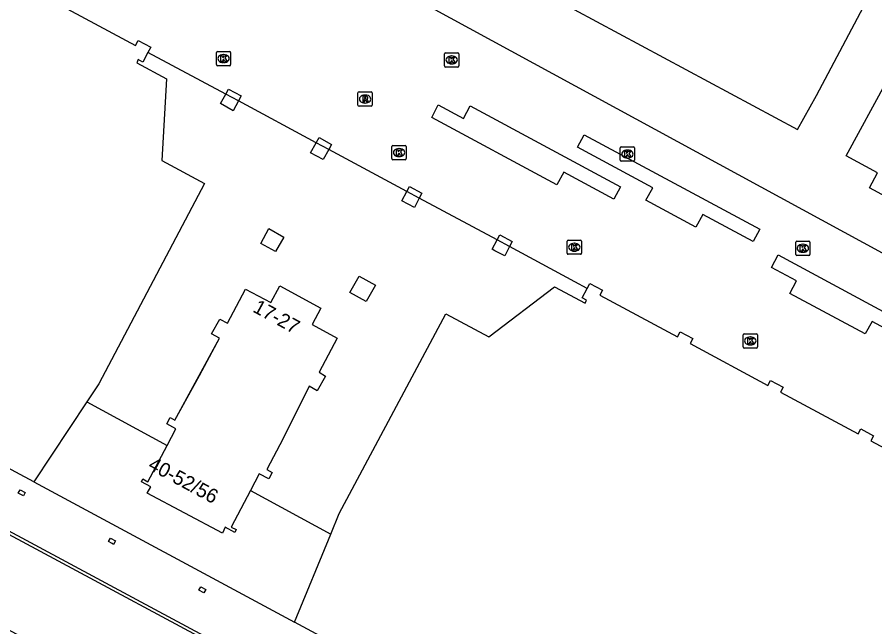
# Model space of a CAD drawing. Extents: x 159489 to 160304, y 383826 to 384530.
# Drawn here: x 159831.2 to 159891.4, y 384203.6 to 384246.5 of the extents above; entities that cross this region are included whole.
import ezdxf

# ---------------------------------------------------------------- set-up
doc = ezdxf.new("R2010")
doc.units = 0
for name, color, linetype in [('IMGEO_Kolk', 7, 'Continuous'), ('IMGEO_Lijnafwatering', 7, 'Continuous'), ('IMGEO_Pand', 7, 'Continuous'), ('IMGEO_Pand_nummerreeks', 7, 'Continuous'), ('IMGEO_Pand_overbouw', 7, 'Continuous'), ('IMGEO_Rioolput', 7, 'Continuous'), ('IMGEO_Voetpad_gesloten', 7, 'Continuous'), ('IMGEO_Voetpad_open', 7, 'Continuous')]:
    doc.layers.add(name, color=color, linetype=linetype)

msp = doc.modelspace()

# ---------------------------------------------------------------- linework, layer by layer
at = {"layer": 'IMGEO_Kolk'}
for p, q in [((159845.183, 384243.138), (159845.183, 384243.99)), ((159845.258, 384244.064), (159846.11, 384244.064)), ((159845.671, 384243.844), (159845.696, 384243.844)), ((159846.184, 384243.99), (159846.184, 384243.138)), ((159861.205, 384243.046), (159861.205, 384243.898)), ((159861.28, 384243.972), (159862.132, 384243.972)), ((159862.206, 384243.898), (159862.206, 384243.046)), ((159845.694, 384243.284), (159845.669, 384243.284)), ((159861.716, 384243.192), (159861.691, 384243.192)), ((159861.693, 384243.752), (159861.718, 384243.752)), ((159846.11, 384243.064), (159845.258, 384243.064)), ((159862.132, 384242.972), (159861.28, 384242.972)), ((159857.51, 384236.536), (159857.51, 384237.388)), ((159857.585, 384237.462), (159858.437, 384237.462)), ((159857.998, 384237.242), (159858.023, 384237.242)), ((159858.511, 384237.388), (159858.511, 384236.536)), ((159873.545, 384236.432), (159873.545, 384237.284)), ((159873.62, 384237.358), (159874.472, 384237.358)), ((159874.546, 384237.284), (159874.546, 384236.432)), ((159858.021, 384236.682), (159857.996, 384236.682)), ((159874.056, 384236.578), (159874.031, 384236.578)), ((159874.033, 384237.138), (159874.058, 384237.138)), ((159858.437, 384236.462), (159857.585, 384236.462)), ((159874.472, 384236.358), (159873.62, 384236.358)), ((159869.819, 384229.889), (159869.819, 384230.741)), ((159869.894, 384230.815), (159870.746, 384230.815)), ((159870.307, 384230.595), (159870.332, 384230.595)), ((159870.82, 384230.741), (159870.82, 384229.889)), ((159885.869, 384229.812), (159885.869, 384230.664)), ((159885.944, 384230.738), (159886.796, 384230.738)), ((159886.87, 384230.664), (159886.87, 384229.812)), ((159870.33, 384230.035), (159870.305, 384230.035)), ((159886.38, 384229.958), (159886.355, 384229.958)), ((159886.357, 384230.518), (159886.382, 384230.518)), ((159870.746, 384229.815), (159869.894, 384229.815)), ((159886.796, 384229.738), (159885.944, 384229.738)), ((159882.177, 384223.308), (159882.177, 384224.16)), ((159882.252, 384224.234), (159883.104, 384224.234)), ((159882.665, 384224.014), (159882.69, 384224.014)), ((159883.178, 384224.16), (159883.178, 384223.308)), ((159882.688, 384223.454), (159882.663, 384223.454)), ((159883.104, 384223.234), (159882.252, 384223.234))]:
    msp.add_line(p, q, dxfattribs=at)
for points in [[(159845.183, 384243.138), (159845.183, 384243.99)], [(159845.258, 384244.064), (159846.11, 384244.064)], [(159846.184, 384243.99), (159846.184, 384243.138)], [(159861.205, 384243.046), (159861.205, 384243.898)], [(159861.28, 384243.972), (159862.132, 384243.972)], [(159862.206, 384243.898), (159862.206, 384243.046)], [(159845.504, 384243.764), (159845.627, 384243.764), (159845.627, 384243.613), (159845.757, 384243.764), (159845.921, 384243.764), (159845.775, 384243.613), (159845.928, 384243.364), (159845.776, 384243.364), (159845.691, 384243.528), (159845.627, 384243.461), (159845.627, 384243.364), (159845.504, 384243.364), (159845.504, 384243.764)], [(159861.526, 384243.672), (159861.649, 384243.672), (159861.649, 384243.521), (159861.779, 384243.672), (159861.943, 384243.672), (159861.797, 384243.521), (159861.95, 384243.272), (159861.798, 384243.272), (159861.713, 384243.436), (159861.649, 384243.369), (159861.649, 384243.272), (159861.526, 384243.272), (159861.526, 384243.672)], [(159846.11, 384243.064), (159845.258, 384243.064)], [(159862.132, 384242.972), (159861.28, 384242.972)], [(159857.51, 384236.536), (159857.51, 384237.388)], [(159857.585, 384237.462), (159858.437, 384237.462)], [(159858.511, 384237.388), (159858.511, 384236.536)], [(159873.545, 384236.432), (159873.545, 384237.284)], [(159873.62, 384237.358), (159874.472, 384237.358)], [(159874.546, 384237.284), (159874.546, 384236.432)], [(159857.831, 384237.162), (159857.954, 384237.162), (159857.954, 384237.011), (159858.084, 384237.162), (159858.248, 384237.162), (159858.102, 384237.011), (159858.255, 384236.762), (159858.103, 384236.762), (159858.018, 384236.926), (159857.954, 384236.859), (159857.954, 384236.762), (159857.831, 384236.762), (159857.831, 384237.162)], [(159873.866, 384237.058), (159873.989, 384237.058), (159873.989, 384236.907), (159874.119, 384237.058), (159874.283, 384237.058), (159874.137, 384236.907), (159874.29, 384236.658), (159874.138, 384236.658), (159874.053, 384236.822), (159873.989, 384236.755), (159873.989, 384236.658), (159873.866, 384236.658), (159873.866, 384237.058)], [(159858.437, 384236.462), (159857.585, 384236.462)], [(159874.472, 384236.358), (159873.62, 384236.358)], [(159869.819, 384229.889), (159869.819, 384230.741)], [(159869.894, 384230.815), (159870.746, 384230.815)], [(159870.82, 384230.741), (159870.82, 384229.889)], [(159885.869, 384229.812), (159885.869, 384230.664)], [(159885.944, 384230.738), (159886.796, 384230.738)], [(159886.87, 384230.664), (159886.87, 384229.812)], [(159870.14, 384230.515), (159870.263, 384230.515), (159870.263, 384230.364), (159870.393, 384230.515), (159870.557, 384230.515), (159870.411, 384230.364), (159870.564, 384230.115), (159870.412, 384230.115), (159870.327, 384230.279), (159870.263, 384230.212), (159870.263, 384230.115), (159870.14, 384230.115), (159870.14, 384230.515)], [(159886.19, 384230.438), (159886.313, 384230.438), (159886.313, 384230.287), (159886.443, 384230.438), (159886.607, 384230.438), (159886.461, 384230.287), (159886.614, 384230.038), (159886.462, 384230.038), (159886.377, 384230.202), (159886.313, 384230.135), (159886.313, 384230.038), (159886.19, 384230.038), (159886.19, 384230.438)], [(159870.746, 384229.815), (159869.894, 384229.815)], [(159886.796, 384229.738), (159885.944, 384229.738)], [(159882.177, 384223.308), (159882.177, 384224.16)], [(159882.252, 384224.234), (159883.104, 384224.234)], [(159882.498, 384223.934), (159882.621, 384223.934), (159882.621, 384223.783), (159882.751, 384223.934), (159882.915, 384223.934), (159882.769, 384223.783), (159882.922, 384223.534), (159882.77, 384223.534), (159882.685, 384223.698), (159882.621, 384223.631), (159882.621, 384223.534), (159882.498, 384223.534), (159882.498, 384223.934)], [(159883.178, 384224.16), (159883.178, 384223.308)], [(159883.104, 384223.234), (159882.252, 384223.234)]]:
    msp.add_lwpolyline(points, dxfattribs=at)
for centre, start, end in [((159845.26, 384243.988), 91.55205, 178.44795), ((159845.26, 384243.988), 91.55205, 178.44795), ((159846.108, 384243.988), 1.55205, 88.44795), ((159846.108, 384243.988), 1.55205, 88.44795), ((159861.282, 384243.896), 91.55205, 178.44795), ((159861.282, 384243.896), 91.55205, 178.44795), ((159862.13, 384243.896), 1.55205, 88.44795), ((159862.13, 384243.896), 1.55205, 88.44795), ((159845.26, 384243.14), 181.55205, 268.44795), ((159845.26, 384243.14), 181.55205, 268.44795), ((159846.108, 384243.14), 271.55205, 358.44795), ((159846.108, 384243.14), 271.55205, 358.44795), ((159861.282, 384243.048), 181.55205, 268.44795), ((159861.282, 384243.048), 181.55205, 268.44795), ((159862.13, 384243.048), 271.55205, 358.44795), ((159862.13, 384243.048), 271.55205, 358.44795), ((159857.587, 384237.386), 91.55205, 178.44795), ((159857.587, 384237.386), 91.55205, 178.44795), ((159858.435, 384237.386), 1.55205, 88.44795), ((159858.435, 384237.386), 1.55205, 88.44795), ((159873.622, 384237.282), 91.55205, 178.44795), ((159873.622, 384237.282), 91.55205, 178.44795), ((159874.47, 384237.282), 1.55205, 88.44795), ((159874.47, 384237.282), 1.55205, 88.44795), ((159857.587, 384236.538), 181.55205, 268.44795), ((159857.587, 384236.538), 181.55205, 268.44795), ((159858.435, 384236.538), 271.55205, 358.44795), ((159858.435, 384236.538), 271.55205, 358.44795), ((159873.622, 384236.434), 181.55205, 268.44795), ((159873.622, 384236.434), 181.55205, 268.44795), ((159874.47, 384236.434), 271.55205, 358.44795), ((159874.47, 384236.434), 271.55205, 358.44795), ((159869.896, 384230.739), 91.55205, 178.44795), ((159869.896, 384230.739), 91.55205, 178.44795), ((159870.744, 384230.739), 1.55205, 88.44795), ((159870.744, 384230.739), 1.55205, 88.44795), ((159885.946, 384230.662), 91.55205, 178.44795), ((159885.946, 384230.662), 91.55205, 178.44795), ((159886.794, 384230.662), 1.55205, 88.44795), ((159886.794, 384230.662), 1.55205, 88.44795), ((159869.896, 384229.891), 181.55205, 268.44795), ((159869.896, 384229.891), 181.55205, 268.44795), ((159870.744, 384229.891), 271.55205, 358.44795), ((159870.744, 384229.891), 271.55205, 358.44795), ((159885.946, 384229.814), 181.55205, 268.44795), ((159885.946, 384229.814), 181.55205, 268.44795), ((159886.794, 384229.814), 271.55205, 358.44795), ((159886.794, 384229.814), 271.55205, 358.44795), ((159882.254, 384224.158), 91.55205, 178.44795), ((159882.254, 384224.158), 91.55205, 178.44795), ((159883.102, 384224.158), 1.55205, 88.44795), ((159883.102, 384224.158), 1.55205, 88.44795), ((159882.254, 384223.31), 181.55205, 268.44795), ((159882.254, 384223.31), 181.55205, 268.44795), ((159883.102, 384223.31), 271.55205, 358.44795), ((159883.102, 384223.31), 271.55205, 358.44795)]:
    msp.add_arc(centre, 0.0765, start, end, dxfattribs=at)
for centre, major_axis, ratio, start_param, end_param in [((159845.67, 384243.564), (-0.387, 0.002), 0.722429, 4.712389, 7.853982), ((159845.695, 384243.564), (-0.39, 0.002), 0.717154, 1.570796, 4.712389), ((159861.692, 384243.472), (-0.387, 0.002), 0.722429, 4.712389, 7.853982), ((159861.717, 384243.472), (-0.39, 0.002), 0.717154, 1.570796, 4.712389), ((159857.997, 384236.962), (-0.387, 0.002), 0.722429, 4.712389, 7.853982), ((159858.022, 384236.962), (-0.39, 0.002), 0.717154, 1.570796, 4.712389), ((159874.032, 384236.858), (-0.387, 0.002), 0.722429, 4.712389, 7.853982), ((159874.057, 384236.858), (-0.39, 0.002), 0.717154, 1.570796, 4.712389), ((159870.306, 384230.315), (-0.387, 0.002), 0.722429, 4.712389, 7.853982), ((159870.331, 384230.315), (-0.39, 0.002), 0.717154, 1.570796, 4.712389), ((159886.356, 384230.238), (-0.387, 0.002), 0.722429, 4.712389, 7.853982), ((159886.381, 384230.238), (-0.39, 0.002), 0.717154, 1.570796, 4.712389), ((159882.664, 384223.734), (-0.387, 0.002), 0.722429, 4.712389, 7.853982), ((159882.689, 384223.734), (-0.39, 0.002), 0.717154, 1.570796, 4.712389)]:
    msp.add_ellipse(centre, major_axis=major_axis, ratio=ratio, start_param=start_param, end_param=end_param, dxfattribs=at)
at = {"layer": 'IMGEO_Lijnafwatering'}
for points in [[(159839.597, 384205.535), (159822.818, 384214.548)], [(159856.376, 384196.522), (159839.597, 384205.535)]]:
    msp.add_lwpolyline(points, dxfattribs=at)
at = {"layer": 'IMGEO_Pand'}
for points in [[(159827.698, 384250.814), (159833.176, 384247.87), (159833.369, 384248.239), (159834.25, 384247.76), (159834.054, 384247.399), (159839.497, 384244.475), (159839.69, 384244.84), (159840.57, 384244.359), (159840.376, 384244.002), (159840.01, 384243.32), (159839.694, 384243.496), (159839.589, 384243.272), (159841.688, 384242.153), (159841.346, 384236.404), (159844.358, 384234.78), (159836.928, 384220.726), (159836.092, 384219.448), (159832.355, 384213.828)], [(159909.661, 384232.979), (159911.807, 384231.817), (159908.923, 384226.496), (159906.871, 384227.608), (159906.782, 384227.656), (159907.444, 384228.878), (159903.135, 384231.154), (159902.477, 384229.929), (159895.931, 384233.447), (159895.816, 384233.236), (159893.641, 384234.422), (159893.077, 384233.385), (159891.04, 384234.496), (159891.604, 384235.532), (159889.412, 384236.726), (159892.302, 384242.03), (159894.517, 384240.823), (159897.417, 384246.144), (159912.455, 384238.136), (159909.661, 384232.979)], [(159846.729, 384240.587), (159846.363, 384239.905), (159845.477, 384240.399), (159845.846, 384241.062), (159846.04, 384241.419), (159846.92, 384240.95), (159846.729, 384240.587)], [(159851.793, 384236.955), (159852.199, 384237.648), (159852.39, 384238.01), (159853.26, 384237.539), (159853.07, 384237.18), (159852.69, 384236.473), (159851.793, 384236.955)], [(159832.355, 384213.828), (159806.759, 384227.581), (159806.333, 384226.788), (159806.58, 384226.639), (159806.455, 384226.373), (159790.384, 384235.106)], [(159858.56, 384234.23), (159858.75, 384234.59), (159859.619, 384234.119), (159859.432, 384233.761), (159859.087, 384233.101), (159858.208, 384233.563), (159858.56, 384234.23)], [(159849.929, 384231.009), (159849.342, 384230.013), (159848.299, 384230.579), (159848.871, 384231.633), (159849.929, 384231.009)], [(159865.079, 384231.179), (159865.95, 384230.71), (159865.768, 384230.356), (159865.43, 384229.698), (159864.744, 384230.066), (159864.54, 384230.176), (159864.89, 384230.828), (159865.079, 384231.179)], [(159855.202, 384228.286), (159856.347, 384227.652), (159855.707, 384226.495), (159854.562, 384227.129), (159855.202, 384228.286)], [(159852.52, 384226.034), (159851.9, 384224.877), (159853.673, 384223.928), (159852.392, 384221.529), (159852.846, 384221.265), (159852.263, 384220.225), (159851.696, 384220.543), (159849.86, 384216.884), (159848.722, 384214.704), (159849.102, 384214.486), (159848.871, 384214.044), (159848.188, 384214.403), (159847.571, 384213.231), (159846.211, 384210.648), (159846.574, 384210.481), (159846.476, 384210.283), (159845.788, 384210.654), (159845.618, 384210.218), (159840.331, 384213.041), (159840.567, 384213.482), (159839.913, 384213.826), (159840.01, 384214.04), (159840.363, 384213.832), (159841.725, 384216.397), (159842.342, 384217.559), (159841.698, 384217.902), (159841.928, 384218.344), (159842.274, 384218.155), (159843.988, 384221.304), (159845.41, 384223.915), (159844.841, 384224.225), (159845.425, 384225.265), (159845.952, 384224.987), (159847.232, 384227.377), (159849.008, 384226.426), (159849.631, 384227.59), (159852.52, 384226.034)], [(159850.676, 384203.98), (159853.229, 384210.167), (159853.801, 384211.617), (159861.301, 384225.632), (159864.321, 384224.016), (159868.939, 384227.54), (159871.071, 384226.394), (159871.185, 384226.592), (159870.879, 384226.753), (159871.231, 384227.42), (159871.42, 384227.77), (159872.299, 384227.299), (159872.11, 384226.948), (159877.56, 384224.019), (159877.75, 384224.369), (159878.64, 384223.89), (159878.451, 384223.54), (159883.921, 384220.601), (159884.1, 384220.95), (159884.989, 384220.479), (159884.8, 384220.128), (159890.25, 384217.199), (159890.44, 384217.549), (159891.32, 384217.07), (159891.133, 384216.725), (159896.603, 384213.786)], [(159831.266, 384213.043), (159831.394, 384213.279), (159831.752, 384213.085), (159831.624, 384212.849), (159831.266, 384213.043)], [(159837.867, 384209.494), (159837.61, 384209.644), (159837.751, 384209.884), (159838.102, 384209.679), (159837.964, 384209.442), (159837.867, 384209.494)], [(159844.085, 384206.457), (159844.433, 384206.265), (159844.305, 384206.032), (159843.956, 384206.224), (159844.085, 384206.457)], [(159891.472, 384180.7), (159875.43, 384189.271), (159875.566, 384189.534), (159875.806, 384189.41), (159876.265, 384190.214), (159850.676, 384203.98)]]:
    msp.add_lwpolyline(points, dxfattribs=at)
at = {"layer": 'IMGEO_Pand_overbouw'}
msp.add_lwpolyline([(159836.092, 384219.448), (159841.725, 384216.397), (159842.342, 384217.559), (159841.698, 384217.902), (159841.928, 384218.344), (159842.274, 384218.155), (159845.41, 384223.915), (159844.841, 384224.225), (159845.425, 384225.265), (159845.952, 384224.987), (159847.232, 384227.377), (159849.008, 384226.426), (159849.631, 384227.59), (159852.52, 384226.034), (159851.9, 384224.877), (159853.673, 384223.928), (159852.392, 384221.529), (159852.846, 384221.265), (159852.263, 384220.225), (159851.696, 384220.543), (159849.86, 384216.884), (159848.722, 384214.704), (159849.102, 384214.486), (159848.871, 384214.044), (159848.188, 384214.403), (159847.571, 384213.231), (159853.229, 384210.167), (159853.801, 384211.617), (159861.301, 384225.632), (159864.321, 384224.016), (159868.939, 384227.54), (159871.071, 384226.394), (159871.185, 384226.592), (159870.879, 384226.753), (159871.231, 384227.42), (159870.35, 384227.893), (159865.768, 384230.356), (159864.89, 384230.828), (159859.432, 384233.761), (159858.56, 384234.23), (159853.07, 384237.18), (159852.199, 384237.648), (159846.729, 384240.587), (159845.846, 384241.062), (159840.376, 384244.002), (159840.01, 384243.32), (159839.694, 384243.496), (159839.589, 384243.272), (159841.688, 384242.153), (159841.346, 384236.404), (159844.358, 384234.78), (159836.928, 384220.726)], close=True, dxfattribs=at)
at = {"layer": 'IMGEO_Rioolput'}
for p, q in [((159855.123, 384240.296), (159855.123, 384241.148)), ((159855.198, 384241.222), (159856.05, 384241.222)), ((159855.611, 384241.002), (159855.636, 384241.002)), ((159856.124, 384241.148), (159856.124, 384240.296)), ((159856.05, 384240.222), (159855.198, 384240.222)), ((159855.634, 384240.442), (159855.609, 384240.442))]:
    msp.add_line(p, q, dxfattribs=at)
for points in [[(159855.123, 384240.296), (159855.123, 384241.148)], [(159855.198, 384241.222), (159856.05, 384241.222)], [(159855.712, 384240.92), (159855.46, 384240.922), (159855.46, 384240.522)], [(159855.638, 384240.841), (159855.584, 384240.841), (159855.584, 384240.76)], [(159856.124, 384241.148), (159856.124, 384240.296)], [(159856.05, 384240.222), (159855.198, 384240.222)], [(159855.46, 384240.522), (159855.584, 384240.522), (159855.584, 384240.684), (159855.595, 384240.684)], [(159855.584, 384240.76), (159855.636, 384240.76)], [(159855.642, 384240.655), (159855.713, 384240.522), (159855.853, 384240.522), (159855.788, 384240.648)]]:
    msp.add_lwpolyline(points, dxfattribs=at)
for centre, radius, start, end in [((159855.2, 384241.146), 0.0765, 91.55205, 178.44795), ((159855.2, 384241.146), 0.0765, 91.55205, 178.44795), ((159855.644, 384240.745), 0.0964, 77.00612, 93.18647), ((159855.658, 384240.802), 0.0378, 276.66336, 79.67722), ((159855.711, 384240.81), 0.109, 350.36119, 89.41601), ((159855.709, 384240.81), 0.112, 277.58423, 350.98172), ((159856.048, 384241.146), 0.0765, 1.55205, 88.44795), ((159856.048, 384241.146), 0.0765, 1.55205, 88.44795), ((159855.2, 384240.298), 0.0765, 181.55205, 268.44795), ((159855.2, 384240.298), 0.0765, 181.55205, 268.44795), ((159855.594, 384240.631), 0.0533, 26.02933, 88.69889), ((159855.62, 384240.949), 0.19, 274.7715, 282.96867), ((159855.693, 384240.595), 0.108, 29.51342, 73.79051), ((159856.048, 384240.298), 0.0765, 271.55205, 358.44795), ((159856.048, 384240.298), 0.0765, 271.55205, 358.44795)]:
    msp.add_arc(centre, radius, start, end, dxfattribs=at)
for centre, major_axis, ratio, start_param, end_param in [((159855.61, 384240.722), (-0.387, 0.002), 0.722429, 4.712389, 7.853982), ((159855.635, 384240.722), (-0.39, 0.002), 0.717154, 1.570796, 4.712389)]:
    msp.add_ellipse(centre, major_axis=major_axis, ratio=ratio, start_param=start_param, end_param=end_param, dxfattribs=at)
at = {"layer": 'IMGEO_Voetpad_gesloten'}
for points in [[(159860.893, 384252.084), (159885.992, 384238.575), (159887.317, 384240.977), (159890.428, 384246.794), (159893.567, 384252.708), (159895.332, 384251.761), (159895.356, 384251.808), (159897.071, 384250.898)], [(159909.635, 384220.285), (159909.594, 384220.307), (159909.525, 384220.345), (159858.696, 384248.021)]]:
    msp.add_lwpolyline(points, dxfattribs=at)
at = {"layer": 'IMGEO_Voetpad_open'}
for points in [[(159860.31, 384239.432), (159860.764, 384240.324), (159862.529, 384239.358), (159862.998, 384240.235), (159873.556, 384234.565), (159873.083, 384233.694), (159869.573, 384235.581), (159869.103, 384234.688), (159860.31, 384239.432)], [(159871.007, 384238.203), (159883.345, 384231.583), (159882.881, 384230.714), (159879.349, 384232.604), (159878.855, 384231.716), (159875.339, 384233.615), (159875.825, 384234.492), (159870.538, 384237.331), (159871.007, 384238.203)], [(159890.081, 384178.186), (159887.304, 384172.975), (159886.537, 384173.398), (159786.238, 384227.228), (159789.088, 384232.417), (159890.081, 384178.186)], [(159884.159, 384228.887), (159884.638, 384229.776), (159895.218, 384224.077), (159894.754, 384223.196), (159891.233, 384225.088), (159890.749, 384224.221), (159885.464, 384227.051), (159885.923, 384227.942), (159884.159, 384228.887)], [(159832.355, 384213.828), (159850.676, 384203.98)]]:
    msp.add_lwpolyline(points, dxfattribs=at)

# ---------------------------------------------------------------- texts
at = {"layer": 'IMGEO_Pand_nummerreeks'}
for s, rotation, p in [('17-27', 331.49535, (159847.674, 384225.813)), ('40-52/56', 331.70161, (159840.315, 384214.765))]:
    msp.add_text(s, height=1, rotation=rotation, dxfattribs=at).set_placement(p)

doc.saveas('drawing.dxf')
